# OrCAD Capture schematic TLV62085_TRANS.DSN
size C; title: TLV62085 High Efficiency 3-A Step-Down Converter; rev: 1.0; note: Datasheet:SLVSD63B      EVM:SLVUAK4; note: Synchronous Step Down Converter; note: in 2-mm × 2-mm VSON Package
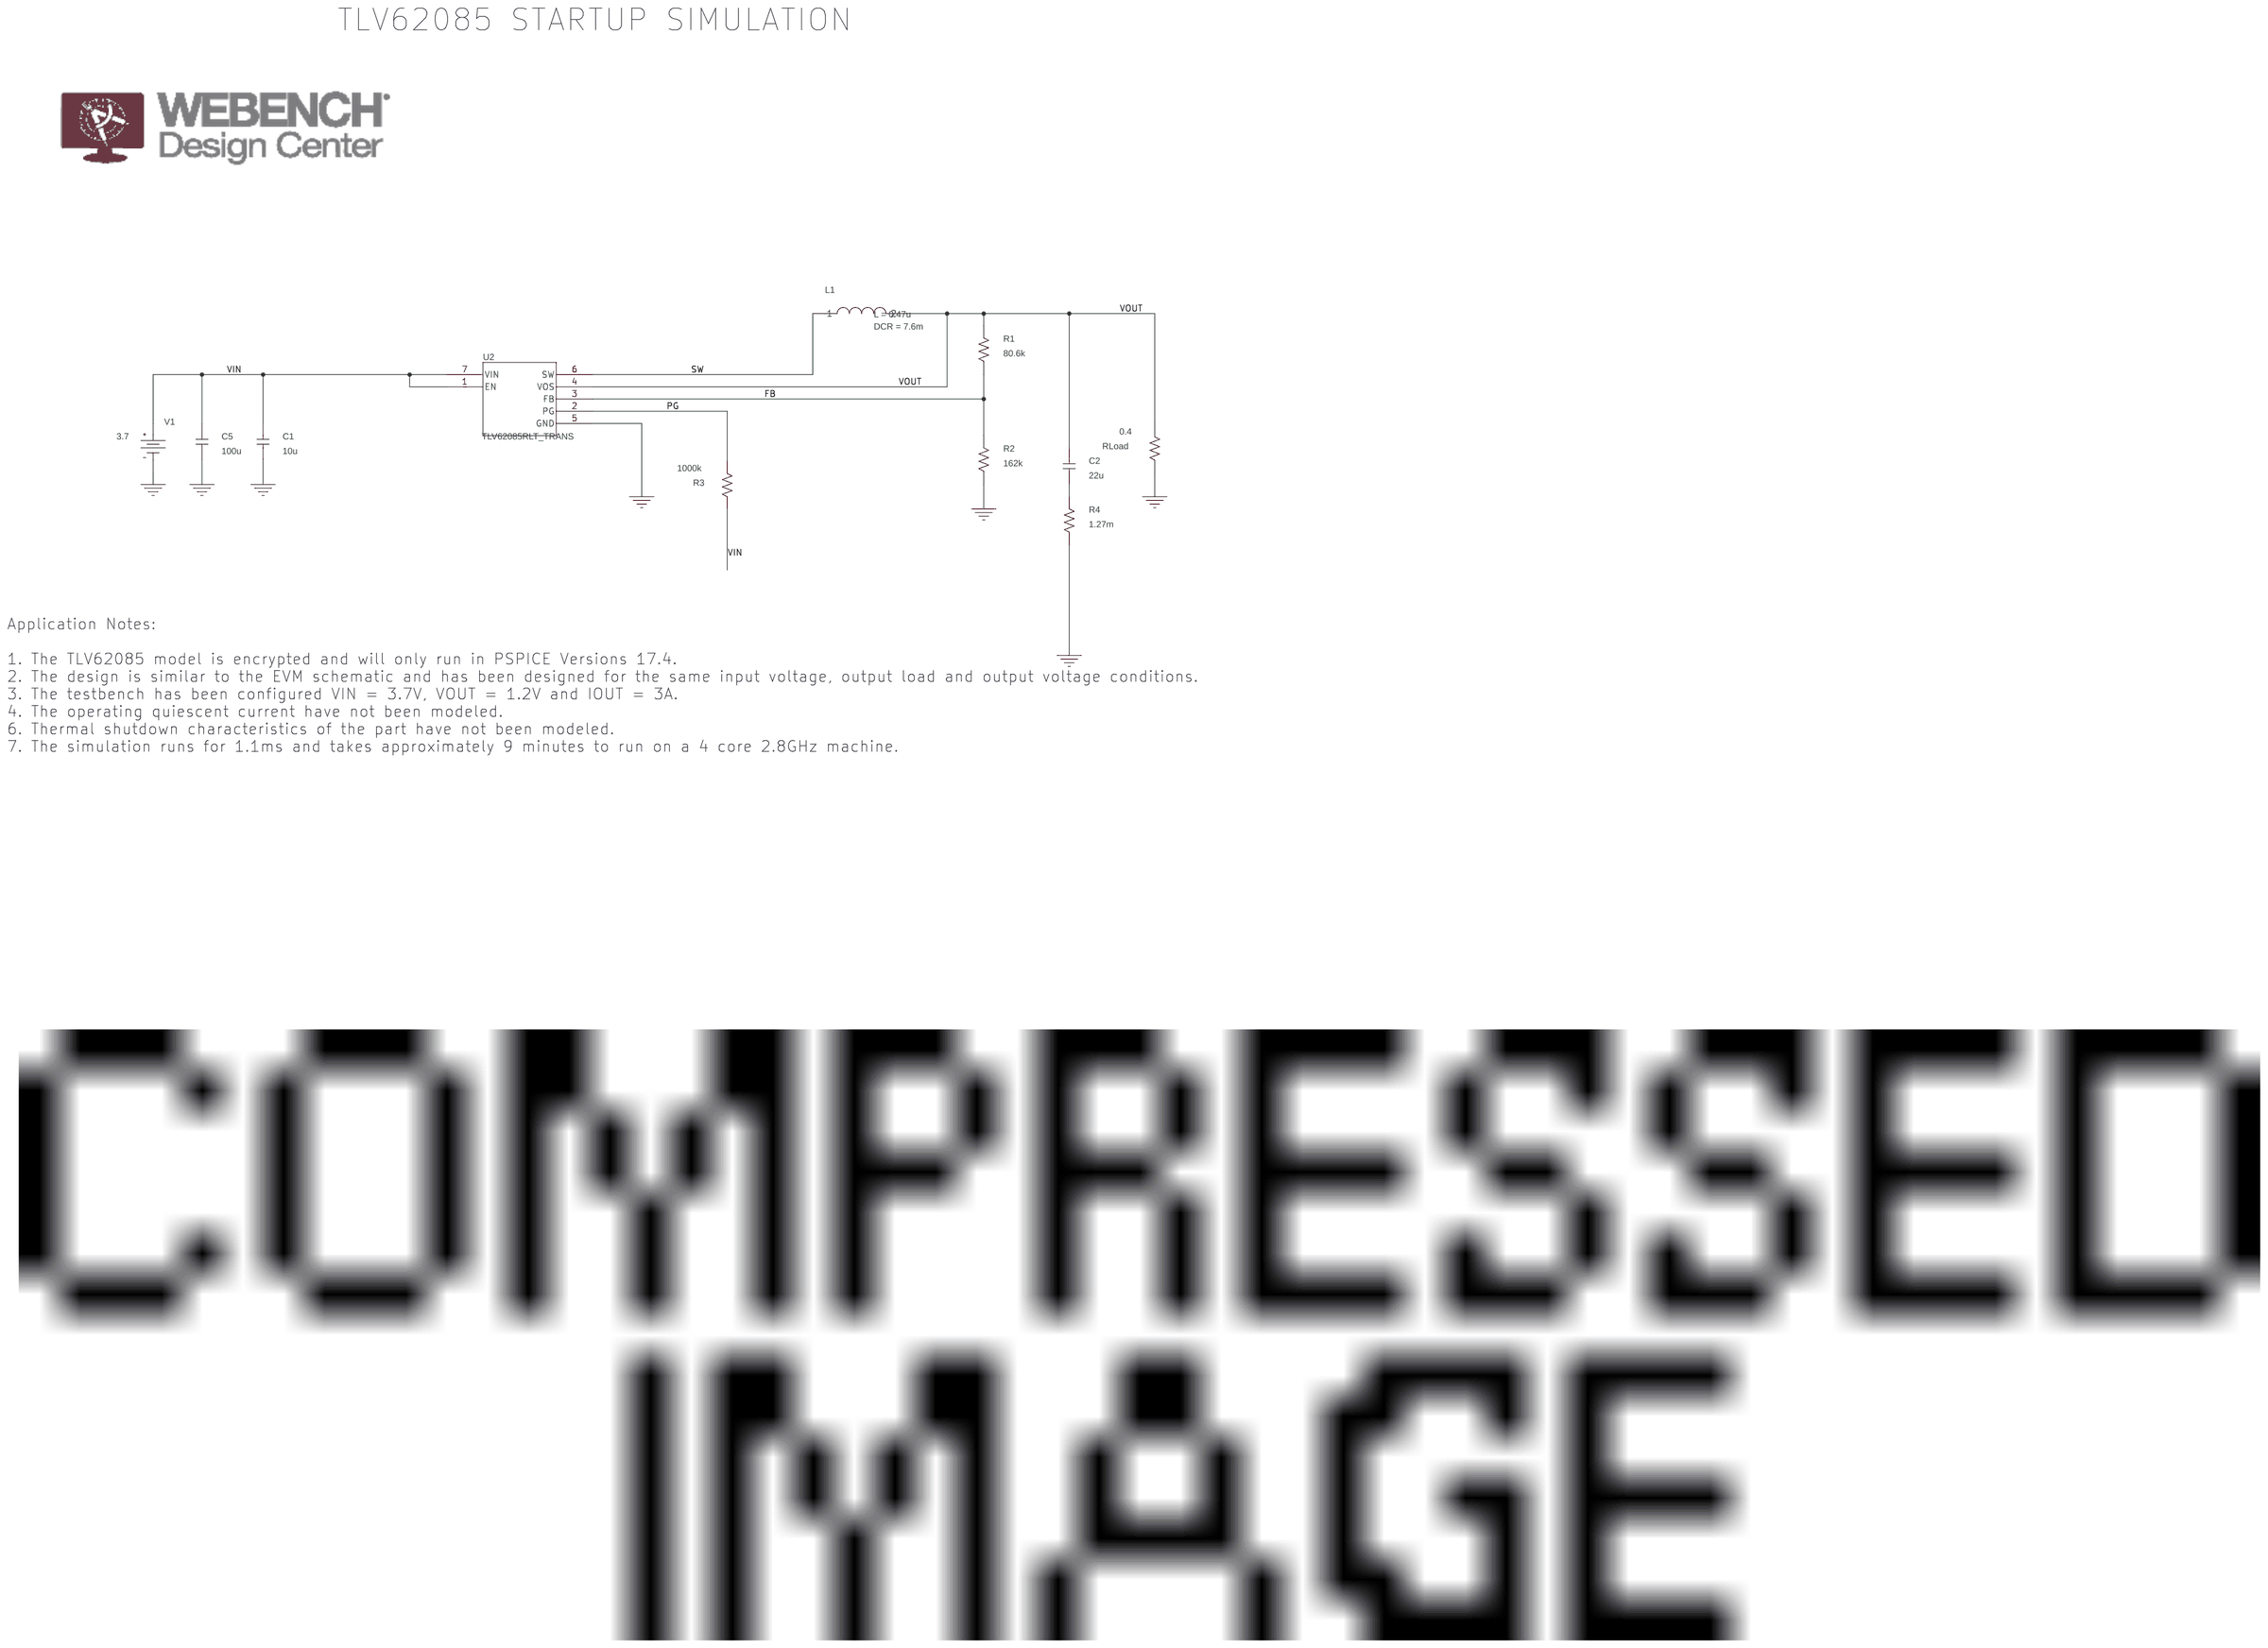
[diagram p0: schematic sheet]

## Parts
C1  10u  [RAD/CK05]
C2  22u  [RAD/CK05]
C5  100u  [RAD/CK05]
L1  LDCR
R1  80.6k  [AX/RC05]
R2  162k  [AX/RC05]
R3  1000k  [AX/RC05]
R4  1.27m  [AX/RC05]
RLoad  0.4  [AX/RC05]
U2  TLV62085RLT_TRANS  [RLT0007A]
V1  VDC

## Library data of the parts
C1 C2 C5 = C
L1 = LDCR: DCR: 7.6m; L: 0.47u
R1-R4 RLoad = R
U2 = TLV62085RLT_TRANS
V1 = VDC: DC: 3.7

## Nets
VIN: C1.2 C5.2 R3.2 U2.1(EN) U2.7(VIN) V1.0(+)
0: C1.1 C5.1 R2.1 R4.1 RLoad.2 U2.5(GND) V1.1(-)
FB: R1.1 R2.2 U2.3(FB)
PG: R3.1 U2.2(PG)
SW: L1.1 U2.6(SW)
VOUT: C2.1 L1.2 R1.2 RLoad.1 U2.4(VOS)
N14563288: C2.2 R4.2

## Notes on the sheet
- TLV62085 STARTUP SIMULATION
- Application Notes:
  1. The TLV62085 model is encrypted and will only run in PSPICE Versions 17.4.
  2. The design is similar to the EVM schematic and has been designed for the same input voltage, output load and output voltage conditions.
  3. The testbench has been configured VIN = 3.7V, VOUT = 1.2V and IOUT = 3A.
  4. The operating quiescent current have not been modeled.
  6. Thermal shutdown characteristics of the part have not been modeled.
  7. The simulation runs for 1.1ms and takes approximately 9 minutes to run on a 4 core 2.8GHz machine.
